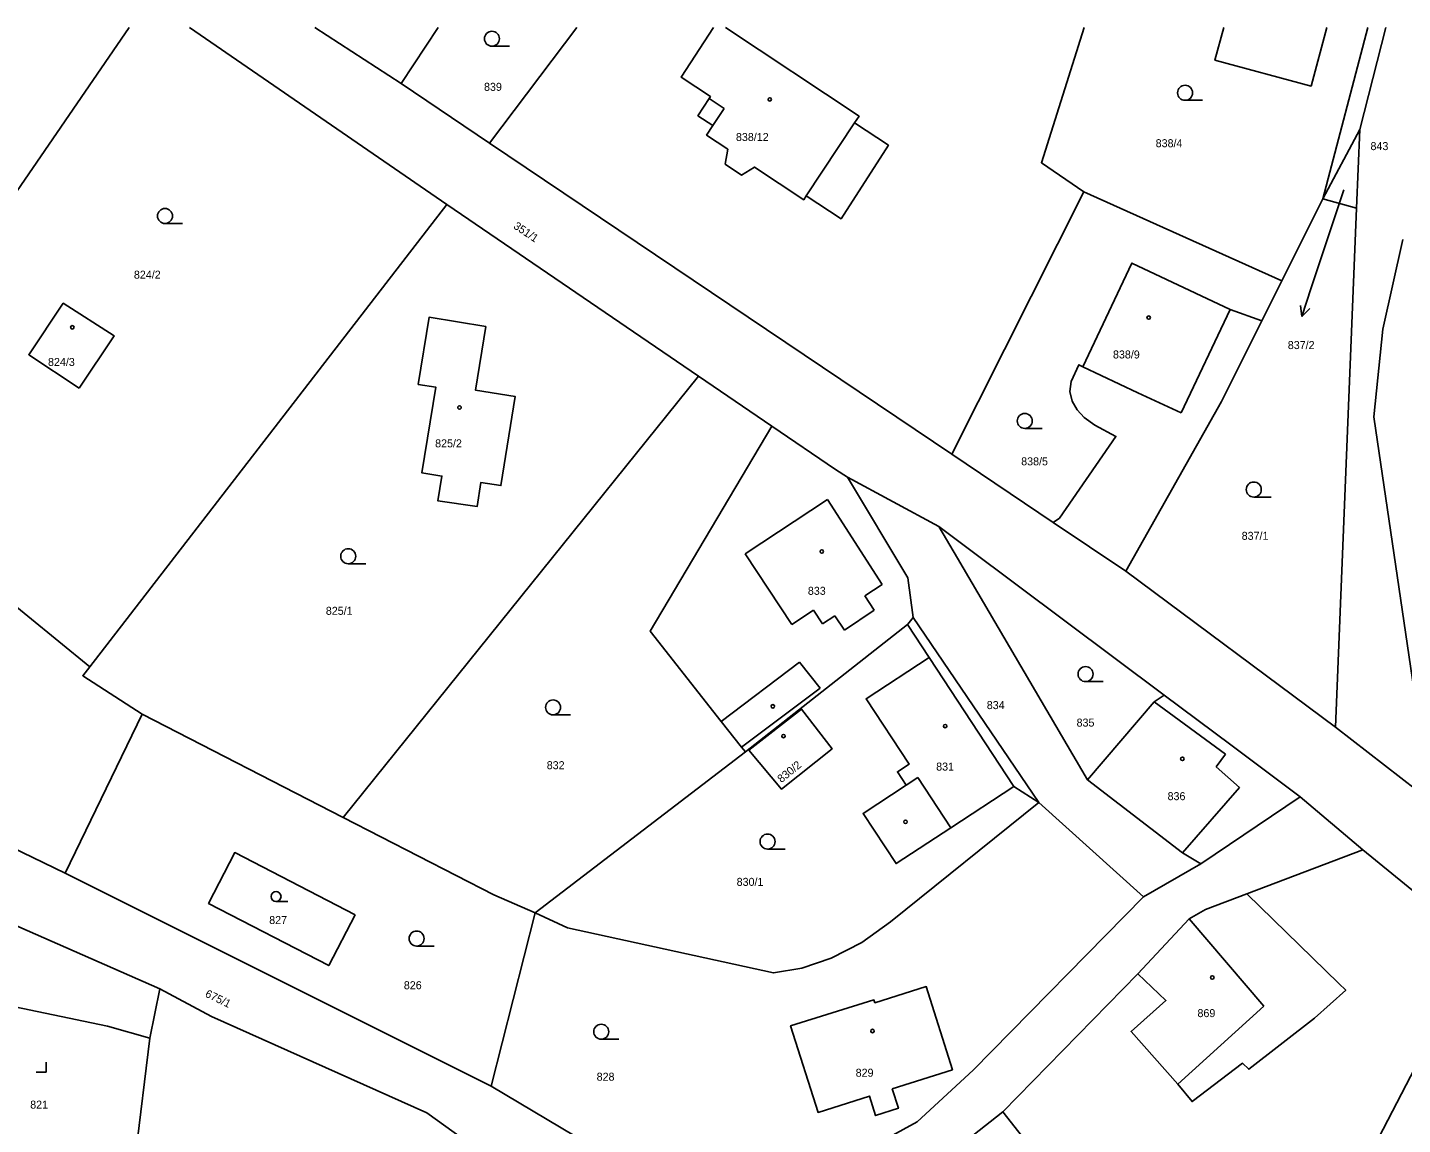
# Model space of a CAD drawing. Extents: x -719706 to -718922, y -950351 to -949651.
# Drawn here: x -719188 to -719050.5, y -949760.8 to -949651 of the extents above; entities that cross this region are included whole.
import ezdxf

# ---------------------------------------------------------------- set-up
doc = ezdxf.new("R2010")
doc.units = 0
doc.layers.add('Doplňující texty', color=7, linetype='Continuous')

msp = doc.modelspace()

# ---------------------------------------------------------------- linework, layer by layer
at = {"layer": 'Doplňující texty'}
for p, q in [((-719177.85, -949651.04), (-719207.33, -949694.07)), ((-719171.79, -949651.04), (-719146.06, -949668.74)), ((-719133.07, -949651.04), (-719141.79, -949662.59)), ((-719058.46, -949668.18), (-719053.96, -949651.04)), ((-719141.56, -949652.91), (-719139.81, -949652.91)), ((-719141.79, -949662.59), (-719150.64, -949656.65)), ((-719118.35, -949659.13), (-719119.83, -949658.14)), ((-719118.35, -949659.13), (-719119.47, -949660.84)), ((-719072.25, -949658.32), (-719070.5, -949658.32)), ((-719105.29, -949660.57), (-719110.13, -949667.88)), ((-719058.46, -949668.18), (-719054.79, -949661.23)), ((-719054.79, -949661.23), (-719055.11, -949669.1)), ((-719095.56, -949693.72), (-719141.79, -949662.59)), ((-719095.56, -949693.72), (-719082.38, -949667.47)), ((-719082.38, -949667.47), (-719062.56, -949676.38)), ((-719056.36, -949667.27), (-719059.63, -949677.09)), ((-719181.78, -949714.99), (-719146.06, -949668.74)), ((-719146.06, -949668.74), (-719120.9, -949685.9)), ((-719062.56, -949676.38), (-719058.46, -949668.18)), ((-719055.11, -949669.1), (-719058.46, -949668.18)), ((-719055.11, -949669.1), (-719057.21, -949721.03)), ((-719174.25, -949670.64), (-719172.5, -949670.64)), ((-719064.57, -949680.39), (-719062.56, -949676.38)), ((-719059.63, -949677.09), (-719060.56, -949679.94)), ((-719067.75, -949679.24), (-719072.65, -949689.58)), ((-719060.56, -949679.94), (-719060.72, -949678.84)), ((-719060.56, -949679.94), (-719059.77, -949679.15)), ((-719076.98, -949687.58), (-719082.49, -949684.98)), ((-719120.9, -949685.9), (-719156.43, -949730.06)), ((-719120.9, -949685.9), (-719113.56, -949690.9)), ((-719076.98, -949687.58), (-719072.65, -949689.58)), ((-719088.28, -949691.14), (-719086.53, -949691.14)), ((-719085.43, -949700.54), (-719095.56, -949693.72)), ((-719181.78, -949714.99), (-719207.33, -949694.07)), ((-719106, -949696), (-719096.87, -949700.95)), ((-719108, -949698.24), (-719116.25, -949703.69)), ((-719108, -949698.24), (-719102.54, -949706.74)), ((-719065.38, -949698), (-719063.63, -949698)), ((-719078.16, -949705.43), (-719085.43, -949700.54)), ((-719155.93, -949704.67), (-719154.18, -949704.67)), ((-719116.25, -949703.69), (-719111.57, -949710.76)), ((-719057.21, -949721.03), (-719078.16, -949705.43)), ((-719104.27, -949707.88), (-719102.54, -949706.74)), ((-719103.33, -949709.31), (-719104.27, -949707.88)), ((-719111.57, -949710.76), (-719109.39, -949709.32)), ((-719109.39, -949709.32), (-719108.5, -949710.68)), ((-719108.5, -949710.68), (-719107.27, -949709.87)), ((-719107.27, -949709.87), (-719106.32, -949711.3)), ((-719106.32, -949711.3), (-719103.33, -949709.31)), ((-719086.88, -949728.55), (-719099.45, -949710.06)), ((-719100.01, -949710.74), (-719116.22, -949723.5)), ((-719097.84, -949714.04), (-719089.38, -949726.94)), ((-719118.63, -949720.44), (-719110.79, -949714.52)), ((-719110.79, -949714.52), (-719108.75, -949717.11)), ((-719108.75, -949717.11), (-719116.59, -949723.03)), ((-719082.2, -949716.46), (-719080.45, -949716.46)), ((-719075.35, -949718.49), (-719068.2, -949723.72)), ((-719184.25, -949735.62), (-719176.55, -949719.73)), ((-719156.43, -949730.06), (-719176.55, -949719.73)), ((-719135.45, -949719.79), (-719133.7, -949719.79)), ((-719045.99, -949729.75), (-719057.21, -949721.03)), ((-719116.22, -949723.5), (-719137.25, -949739.6)), ((-719068.2, -949723.72), (-719069.14, -949725)), ((-719069.14, -949725), (-719066.82, -949727.04)), ((-719100.13, -949726.82), (-719098.97, -949726.05)), ((-719098.97, -949726.05), (-719095.67, -949731.07)), ((-719066.82, -949727.04), (-719072.52, -949733.6)), ((-719060.74, -949727.99), (-719070.69, -949734.68)), ((-719060.74, -949727.99), (-719054.48, -949733.29)), ((-719076.41, -949737.98), (-719086.88, -949728.55)), ((-719114, -949733.21), (-719112.25, -949733.21)), ((-719066.06, -949737.69), (-719054.48, -949733.29)), ((-719054.48, -949733.29), (-719042.89, -949742.78)), ((-719070.69, -949734.68), (-719076.41, -949737.98)), ((-719201.4, -949735.49), (-719174.77, -949747.18)), ((-719141.64, -949756.93), (-719184.25, -949735.62)), ((-719163.15, -949738.46), (-719161.97, -949738.46)), ((-719141.64, -949756.93), (-719137.25, -949739.6)), ((-719071.85, -949740.2), (-719064.36, -949748.94)), ((-719149.09, -949742.91), (-719147.34, -949742.91)), ((-719042.89, -949742.78), (-719066.99, -949789.29)), ((-719090.47, -949759.49), (-719076.98, -949745.69)), ((-719174.77, -949747.18), (-719175.76, -949752.13)), ((-719064.36, -949748.94), (-719072.98, -949756.71)), ((-719175.76, -949752.13), (-719177.82, -949768.78)), ((-719130.63, -949752.23), (-719128.88, -949752.23)), ((-719187.12, -949755.54), (-719186.12, -949755.54)), ((-719186.12, -949755.54), (-719186.12, -949754.54)), ((-719090.47, -949759.49), (-719066.99, -949789.29))]:
    msp.add_line(p, q, dxfattribs=at)
for points in [[(-719150.64, -949656.65), (-719159.26, -949651.04)], [(-719146.94, -949651.04), (-719150.64, -949656.65)], [(-719118.24, -949664.72), (-719117.97, -949663.21), (-719120.1, -949661.79), (-719119.47, -949660.84), (-719120.96, -949659.87), (-719119.83, -949658.14), (-719119.72, -949657.95), (-719122.64, -949656), (-719119.39, -949651.04)], [(-719118.21, -949651.04), (-719104.85, -949659.91), (-719105.29, -949660.57), (-719101.91, -949662.81), (-719106.65, -949670.16), (-719110.13, -949667.88), (-719110.38, -949668.26), (-719115.32, -949664.99), (-719116.61, -949665.79), (-719118.24, -949664.72)], [(-719082.38, -949667.47), (-719086.61, -949664.56), (-719082.33, -949651.04)], [(-719058.06, -949651.04), (-719059.65, -949656.9), (-719069.27, -949654.29), (-719068.39, -949651.04)], [(-719052.16, -949651.04), (-719054.79, -949661.23)], [(-719045.99, -949729.75), (-719048.86, -949720.82), (-719053.39, -949689.97), (-719052.49, -949681.2), (-719050.48, -949672.23)], [(-719085.43, -949700.54), (-719084.82, -949700.11), (-719079.16, -949691.93), (-719081.28, -949690.81), (-719082.35, -949690.03), (-719083.03, -949689.29), (-719083.53, -949688.42), (-719083.79, -949687.44), (-719083.65, -949686.43), (-719082.86, -949684.77), (-719082.49, -949684.98), (-719077.59, -949674.6), (-719067.75, -949679.24), (-719064.57, -949680.39)], [(-719182.82, -949687.12), (-719187.87, -949683.76), (-719184.43, -949678.61), (-719179.32, -949681.88), (-719182.82, -949687.12)], [(-719142.17, -949680.93), (-719143.19, -949687.32), (-719139.23, -949687.96), (-719140.67, -949696.85), (-719142.66, -949696.53), (-719143.05, -949698.96), (-719146.97, -949698.37), (-719146.56, -949695.9), (-719148.57, -949695.57), (-719147.18, -949687.01), (-719148.92, -949686.73), (-719147.84, -949680.02), (-719142.17, -949680.93)], [(-719078.16, -949705.43), (-719068.6, -949688.46), (-719064.57, -949680.39)], [(-719116.22, -949723.5), (-719116.59, -949723.03), (-719118.63, -949720.44), (-719125.73, -949711.42), (-719113.56, -949690.9)], [(-719113.56, -949690.9), (-719107.22, -949695.23), (-719106, -949696)], [(-719099.45, -949710.06), (-719099.96, -949706.08), (-719106, -949696)], [(-719096.87, -949700.95), (-719094.08, -949703.04), (-719074.33, -949717.81)], [(-719082.01, -949726.3), (-719095, -949704.13), (-719096.87, -949700.95)], [(-719099.45, -949710.06), (-719099.96, -949710.7), (-719100.01, -949710.74)], [(-719086.88, -949728.55), (-719089.38, -949726.94), (-719095.67, -949731.07), (-719101.15, -949734.67), (-719104.45, -949729.65), (-719100.13, -949726.82), (-719101.01, -949725.48), (-719099.84, -949724.72), (-719104.14, -949718.17), (-719097.84, -949714.04), (-719100.01, -949710.74)], [(-719176.55, -949719.73), (-719182.47, -949715.88), (-719181.78, -949714.99)], [(-719082.01, -949726.3), (-719075.35, -949718.49), (-719074.33, -949717.81)], [(-719074.33, -949717.81), (-719067.67, -949722.8), (-719060.74, -949727.99)], [(-719115.88, -949723.33), (-719110.6, -949719.21), (-719107.55, -949723.18), (-719112.62, -949727.21), (-719115.88, -949723.33)], [(-719184.25, -949735.62), (-719195.05, -949730.38), (-719210.69, -949725.61)], [(-719070.69, -949734.68), (-719072.52, -949733.6), (-719082.01, -949726.3)], [(-719086.88, -949728.55), (-719101.71, -949740.49), (-719104.58, -949742.54), (-719107.64, -949744.11), (-719110.57, -949745.11), (-719113.39, -949745.6), (-719134, -949741.1), (-719137.25, -949739.6)], [(-719137.25, -949739.6), (-719141.37, -949737.8), (-719156.43, -949730.06)], [(-719155.24, -949739.78), (-719157.87, -949744.86), (-719169.9, -949738.64), (-719167.27, -949733.56), (-719155.24, -949739.78)], [(-719066.06, -949737.69), (-719056.88, -949746.66), (-719056.18, -949747.32), (-719059.3, -949750.11), (-719065.89, -949755.23), (-719066.5, -949754.64), (-719071.55, -949758.47), (-719072.98, -949756.71), (-719077.65, -949751.47), (-719074.17, -949748.37), (-719076.98, -949745.69)], [(-719076.98, -949745.69), (-719071.85, -949740.2), (-719070.2, -949739.26), (-719066.06, -949737.69)], [(-719076.41, -949737.98), (-719093.44, -949755.34), (-719099.03, -949760.49), (-719101.84, -949762.01), (-719115.71, -949767.02), (-719123.28, -949767.87), (-719141.64, -949756.93)], [(-719175.76, -949752.13), (-719179.99, -949750.91), (-719190.89, -949748.65), (-719197.5, -949750), (-719196.74, -949746.24), (-719200.64, -949745.44), (-719201.8, -949751.13), (-719201.82, -949751.19), (-719202.67, -949755.38), (-719193.56, -949762.7), (-719177.82, -949768.78)], [(-719174.77, -949747.18), (-719169.6, -949749.95), (-719148.07, -949759.6), (-719140.69, -949764.91)], [(-719101.53, -949757.2), (-719100.91, -949759.14), (-719103.19, -949759.86), (-719103.81, -949757.92), (-719108.95, -949759.55), (-719111.7, -949750.9), (-719103.36, -949748.3), (-719103.27, -949748.59), (-719098.13, -949746.97), (-719095.51, -949755.29), (-719101.53, -949757.2)], [(-719108.05, -949771.11), (-719101.21, -949767.96), (-719090.47, -949759.49)]]:
    msp.add_lwpolyline(points, dxfattribs=at)
for centre, radius in [((-719141.56, -949652.16), 0.75), ((-719072.25, -949657.57), 0.75), ((-719113.78, -949658.23), 0.175), ((-719174.25, -949669.89), 0.75), ((-719075.89, -949680.05), 0.175), ((-719183.52, -949681.02), 0.175), ((-719144.8, -949689.05), 0.175), ((-719088.28, -949690.39), 0.75), ((-719065.38, -949697.25), 0.75), ((-719155.93, -949703.92), 0.75), ((-719108.58, -949703.45), 0.175), ((-719082.2, -949715.71), 0.75), ((-719135.45, -949719.04), 0.75), ((-719113.47, -949718.93), 0.175), ((-719096.24, -949720.91), 0.175), ((-719112.4, -949721.91), 0.175), ((-719072.52, -949724.18), 0.175), ((-719100.2, -949730.49), 0.175), ((-719114, -949732.46), 0.75), ((-719163.15, -949737.96), 0.502), ((-719149.09, -949742.16), 0.75), ((-719069.53, -949746.05), 0.175), ((-719130.63, -949751.48), 0.75), ((-719103.51, -949751.41), 0.175)]:
    msp.add_circle(centre, radius, dxfattribs=at)

# ---------------------------------------------------------------- texts
for s, p in [('839', (-719142.35, -949657.37)), ('838/12', (-719117.16, -949662.39)), ('838/4', (-719075.19, -949663.01)), ('843', (-719053.71, -949663.3)), ('824/2', (-719177.36, -949676.16)), ('837/2', (-719061.98, -949683.2)), ('824/3', (-719185.95, -949684.89)), ('838/9', (-719079.46, -949684.14)), ('825/2', (-719147.24, -949693.03)), ('838/5', (-719088.64, -949694.83)), ('837/1', (-719066.59, -949702.28)), ('833', (-719109.97, -949707.78)), ('825/1', (-719158.17, -949709.78)), ('834', (-719092.08, -949719.21)), ('835', (-719083.1, -949720.96)), ('832', (-719136.08, -949725.22)), ('831', (-719097.14, -949725.36)), ('836', (-719074, -949728.32)), ('830/1', (-719117.09, -949736.89)), ('827', (-719163.83, -949740.71)), ('826', (-719150.37, -949747.23)), ('869', (-719071.01, -949750.02)), ('828', (-719131.09, -949756.38)), ('829', (-719105.19, -949755.98)), ('821', (-719187.73, -949759.17))]:
    msp.add_text(s, height=0.8, dxfattribs=at).set_placement(p)
for s, rotation, p in [('351/1', 326, (-719139.48, -949671.07)), ('830/2', 39, (-719112.62, -949726.62)), ('675/1', 334, (-719170.31, -949747.94))]:
    msp.add_text(s, height=0.8, rotation=rotation, dxfattribs=at).set_placement(p)

doc.saveas('drawing.dxf')
